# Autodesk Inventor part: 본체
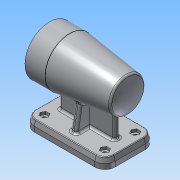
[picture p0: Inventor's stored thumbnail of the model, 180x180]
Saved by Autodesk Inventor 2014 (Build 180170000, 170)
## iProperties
Created: 2017-01
Part Number: 본체
Material: 알루미늄 6061
Document SubType Name: Modeling
Designer: 702
Density: 2.71 g/cm^3
Appearance: 알루미늄 - 평지
Mass: 794.784 g
Surface Area: 662.73 cm^2
Volume: 293.278 cm^3
Author: 702
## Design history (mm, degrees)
sketch "스케치1"
  geometry: L1 (-42, 35)-(42, 35); L2 (56, 21)-(56, -21); L3 (42, -35)-(-42, -35); L4 (-56, -21)-(-56, 21); A1 r 14 centre (-42, -21) between (-56, -21) and (-42, -35); A2 r 14 centre (-42, 21) between (-42, 35) and (-56, 21); A3 r 14 centre (42, 21) between (56, 21) and (42, 35); A4 r 14 centre (42, -21) between (42, -35) and (56, -21); 6 further points
  constraints: 8 end point, 8 point on circle, 8 tangent, 6 point on line, 4 centre point, 3 equal radius, 2 midpoint, 2 parallel, 1 horizontal, 1 horizontal alignment, 1 perpendicular, 1 vertical alignment
extrude "돌출3" join sketch "스케치1" distance "d56" = 7; taper "d57" = 0 deg
sketch "스케치6"
  geometry: L1 (-56, 21)-(-56, -21) reference; L2 (-42, -35)-(42, -35) reference; L3 (56, -21)-(56, 21) reference; L4 (42, 35)-(-42, 35) reference; A1 r 14 centre (-42, -21) between (-56, -21) and (-42, -35) reference; A2 r 14 centre (42, -21) between (42, -35) and (56, -21) reference; A3 r 14 centre (42, 21) between (56, 21) and (42, 35) reference; A4 r 14 centre (-42, 21) between (-42, 35) and (-56, 21) reference; 1 further point
extrude "돌출4" join sketch "스케치6" distance "d58" = 7; taper "d59" = -15 deg
sketch "스케치7"
  geometry: L1 (56, 108)-(28, 108); L2 (28, 108)-(-50.331, 98.382); L3 (55, 95)-(41, 95); L4 (38, 98)-(-10, 98); L5 (-13, 95)-(-24.7, 95); L6 (-25, 91.5)-(-42.7, 91.5); L7 (-43, 90)-(-46.7, 90); L8 (-47, 84.5)-(-49, 84.5); L9 (0, 74)-(72.161, 74); L10 (-50, 83.5)-(-50, 74); L11 (-47, 89.7)-(-47, 84.5); L12 (-43, 91.2)-(-43, 90); L13 (-25, 94.7)-(-25, 91.5); L14 (-13, 95)-(-13, 95); L15 (41, 95)-(41, 95); L16 (56, 108)-(56, 96); L17 (-50, 74)-(-56, 74); L18 (-50, 83.5)-(-49, 84.5); L19 (55, 95)-(56, 96); A1 r 80 centre (24, 74) between (-52.847, 96.238) and (-56, 74); A2 r 3 centre (-10, 95) between (-10, 98) and (-13, 95); A3 r 3 centre (38, 95) between (41, 95) and (38, 98); A4 r 0.3 centre (-46.7, 89.7) between (-46.7, 90) and (-47, 89.7); A5 r 0.3 centre (-42.7, 91.2) between (-42.7, 91.5) and (-43, 91.2); A6 r 0.3 centre (-24.7, 94.7) between (-24.7, 95) and (-25, 94.7); A7 r 3 centre (-49.965, 95.405) between (-50.331, 98.382) and (-52.847, 96.238); 4 further points
  constraints: 38 end point, 15 point on circle, 12 tangent, 10 parallel, 7 centre point, 5 point on line, 2 equal radius, 2 perpendicular
revolve "회전2" sketch "스케치7" stored, may be unused: angle "d94" = 90 deg
sketch "스케치8"
  geometry: L1 (38, -4)-(-38, -4); L2 (38, -4)-(38, 4); L3 (38, 4)-(-38, 4); L4 (-38, -4)-(-38, 4); L5 (44.887, -16)-(47.774, -21); L6 (47.774, -21)-(44.887, -26); L7 (44.887, -26)-(39.113, -26); L8 (39.113, -26)-(36.226, -21); L9 (36.226, -21)-(39.113, -16); L10 (39.113, -16)-(44.887, -16); L11 (44.887, 26)-(47.774, 21); L12 (47.774, 21)-(44.887, 16); L13 (44.887, 16)-(39.113, 16); L14 (39.113, 16)-(36.226, 21); L15 (36.226, 21)-(39.113, 26); L16 (39.113, 26)-(44.887, 26); L17 (-39.113, 26)-(-36.226, 21); L18 (-36.226, 21)-(-39.113, 16); L19 (-39.113, 16)-(-44.887, 16); L20 (-44.887, 16)-(-47.774, 21); L21 (-47.774, 21)-(-44.887, 26); L22 (-44.887, 26)-(-39.113, 26); L23 (-39.113, -16)-(-36.226, -21); L24 (-36.226, -21)-(-39.113, -26); L25 (-39.113, -26)-(-44.887, -26); L26 (-44.887, -26)-(-47.774, -21); L27 (-47.774, -21)-(-44.887, -16); L28 (-44.887, -16)-(-39.113, -16); 13 further points
  constraints: 56 end point, 4 coincident, 4 midpoint, 3 perpendicular, 52 other
extrude "돌출5" join sketch "스케치8" stored distance "d103" = 7; taper "d104" = 0 deg
sketch "스케치9"
  geometry: L1 (23, 14)-(16.054, 53.392); 1 further point
  constraints: 2 end point
feature "리브1" sketch "스케치9" dims "d108" = 1, "d109" = 8, "d110" = 0, "d111" = 0, "d112" = 1, "d113" = 1
sketch "스케치10"
  geometry: 5 further points
hole "구멍1" sketch "스케치10" at (26, 0), (0, 26), (-26, 0), (0, -26) diameter "d115" = 3.242; stored, may be unused: countersink angle "d119" = 90 deg, drill point angle "d121" = 118 deg; dims "d116" = 8, "d117" = 4, "d118" = 2, "d120" = 11
extrude "돌출6" cut sketch "스케치8" distance "d122" = 4; taper "d123" = 0 deg
hole "구멍2" sketch "스케치8" diameter "d124" = 5; stored, may be unused: countersink angle "d128" = 90 deg, drill point angle "d130" = 118 deg; dims "d125" = 8, "d126" = 4, "d127" = 2, "d129" = 11
fillet "모깎기1" dims "d131" = 1, "d132" = 3
fillet "모깎기2" dims "d133" = 3
sketch "스케치11"
  geometry: 2 further points
  constraints: 1 other
feature "엠보싱2" sketch "스케치11" dims "d135" = 0.5, "d136" = 0
node "솔리드1"
mirror "대칭1"
